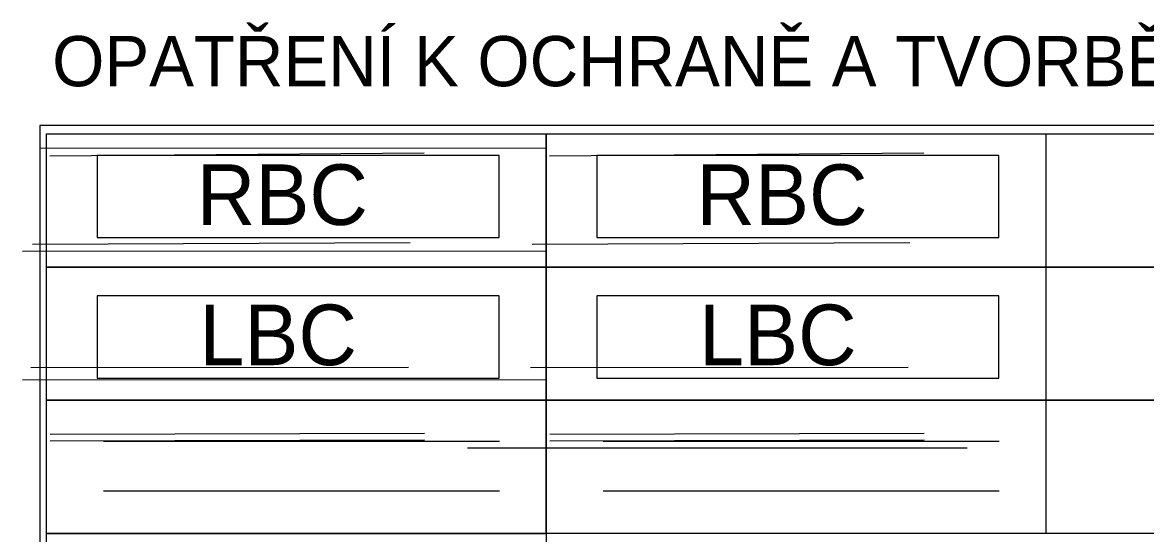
# Model space of a CAD drawing. Extents: x -478232 to -472707, y -1118753 to -1113967.
# Drawn here: x -474027.4 to -473656.7, y -1118533.6 to -1118364.9 of the extents above; entities that cross this region are included whole.
import ezdxf

# ---------------------------------------------------------------- set-up
doc = ezdxf.new("R2010")
doc.units = 0
for name, color, linetype in [('RBC', 7, 'Continuous'), ('uses_LBK', 7, 'Continuous'), ('uses_RBK', 7, 'Continuous'), ('Z_razitko', 7, 'Continuous')]:
    doc.layers.add(name, color=color, linetype=linetype)

msp = doc.modelspace()

# ---------------------------------------------------------------- linework, layer by layer
at = {"layer": 'uses_LBK'}
for points in [[(-474002.753, -1118455.15), (-474002.753, -1118482.31), (-473870.02, -1118482.31), (-473870.02, -1118455.15), (-474002.753, -1118455.15)], [(-473837.824, -1118455.15), (-473837.824, -1118482.31), (-473705.091, -1118482.31), (-473705.091, -1118455.15), (-473837.824, -1118455.15)]]:
    msp.add_lwpolyline(points, dxfattribs=at)
at = {"layer": 'uses_RBK'}
for p, q in [((-474000.719, -1118503.096), (-473869.977, -1118503.096)), ((-473835.79, -1118503.096), (-473705.048, -1118503.096)), ((-474000.719, -1118519.542), (-473869.977, -1118519.542)), ((-473835.79, -1118519.542), (-473705.048, -1118519.542))]:
    msp.add_line(p, q, dxfattribs=at)
at = {"layer": 'Z_razitko'}
for p, q in [((-474021.692, -1118398.926), (-474021.694, -1118668.121)), ((-473059.49, -1118398.927), (-474021.692, -1118398.927)), ((-474021.69, -1118406.292), (-473854.384, -1118406.363)), ((-474018.408, -1118408.948), (-473894.826, -1118407.902)), ((-473853.479, -1118408.948), (-473729.896, -1118407.902)), ((-473854.58, -1118440.411), (-474027.421, -1118440.457)), ((-473899.475, -1118437.59), (-474024.15, -1118438.22)), ((-473734.546, -1118437.59), (-473859.22, -1118438.22)), ((-473899.951, -1118478.817), (-474024.624, -1118478.935)), ((-473735.022, -1118478.817), (-473859.695, -1118478.935)), ((-473854.565, -1118482.915), (-474027.406, -1118482.962)), ((-474018.323, -1118503.028), (-473894.739, -1118502.672)), ((-474018.299, -1118500.816), (-473894.714, -1118500.459)), ((-473853.394, -1118503.028), (-473729.81, -1118502.672)), ((-473853.369, -1118500.816), (-473729.785, -1118500.459)), ((-473880.517, -1118505.333), (-473715.6, -1118505.333))]:
    msp.add_line(p, q, dxfattribs=at)
for points in [[(-474019.489, -1118401.669), (-473854.571, -1118401.669), (-473854.571, -1118401.669), (-473854.571, -1118445.65), (-474019.489, -1118445.65)], [(-473854.571, -1118401.67), (-473689.65, -1118401.67), (-473689.65, -1118401.67), (-473689.65, -1118445.65), (-473854.571, -1118445.65)], [(-473854.571, -1118401.67), (-473061.141, -1118401.67), (-473061.141, -1118445.65), (-473854.571, -1118445.65)], [(-474019.489, -1118445.65), (-473854.571, -1118445.65), (-473854.571, -1118445.65), (-473854.571, -1118489.631), (-474019.489, -1118489.631)], [(-473854.571, -1118445.651), (-473061.141, -1118445.651), (-473061.141, -1118489.631), (-473854.571, -1118489.631)], [(-473854.571, -1118445.651), (-473689.65, -1118445.651), (-473689.65, -1118445.651), (-473689.65, -1118489.631), (-473854.571, -1118489.631)], [(-474019.489, -1118489.631), (-473854.571, -1118489.631), (-473854.571, -1118489.631), (-473854.571, -1118533.611), (-474019.489, -1118533.611)], [(-473854.571, -1118489.632), (-473061.141, -1118489.632), (-473061.141, -1118533.611), (-473854.571, -1118533.611)], [(-473854.571, -1118489.632), (-473689.65, -1118489.632), (-473689.65, -1118489.632), (-473689.65, -1118533.611), (-473854.571, -1118533.611)], [(-474019.489, -1118533.611), (-473854.571, -1118533.611), (-473854.571, -1118533.611), (-473854.571, -1118577.592), (-474019.489, -1118577.592)]]:
    msp.add_lwpolyline(points, close=True, dxfattribs=at)
for points in [[(-474002.753, -1118408.766), (-474002.753, -1118435.926), (-473870.02, -1118435.926), (-473870.02, -1118408.766), (-474002.753, -1118408.766)], [(-473837.824, -1118408.766), (-473837.824, -1118435.926), (-473705.091, -1118435.926), (-473705.091, -1118408.766), (-473837.824, -1118408.766)]]:
    msp.add_lwpolyline(points, dxfattribs=at)

# ---------------------------------------------------------------- texts
at = {"layer": 'RBC'}
for p in [(-473969.869, -1118431.746), (-473804.94, -1118431.746)]:
    msp.add_text('RBC', height=20, rotation=359.99999, dxfattribs=at).set_placement(p)
at = {"layer": 'uses_LBK'}
for p in [(-473969.039, -1118478.033), (-473804.11, -1118478.033)]:
    msp.add_text('LBC', height=20, rotation=359.99999, dxfattribs=at).set_placement(p)
at = {"layer": 'Z_razitko'}
msp.add_text('OPATŘENÍ K OCHRANĚ A TVORBĚ ŽIVOTNÍHO PROSTŘEDÍ', height=16.5709, dxfattribs=at).set_placement((-474017.609, -1118385.947))

doc.saveas('drawing.dxf')
